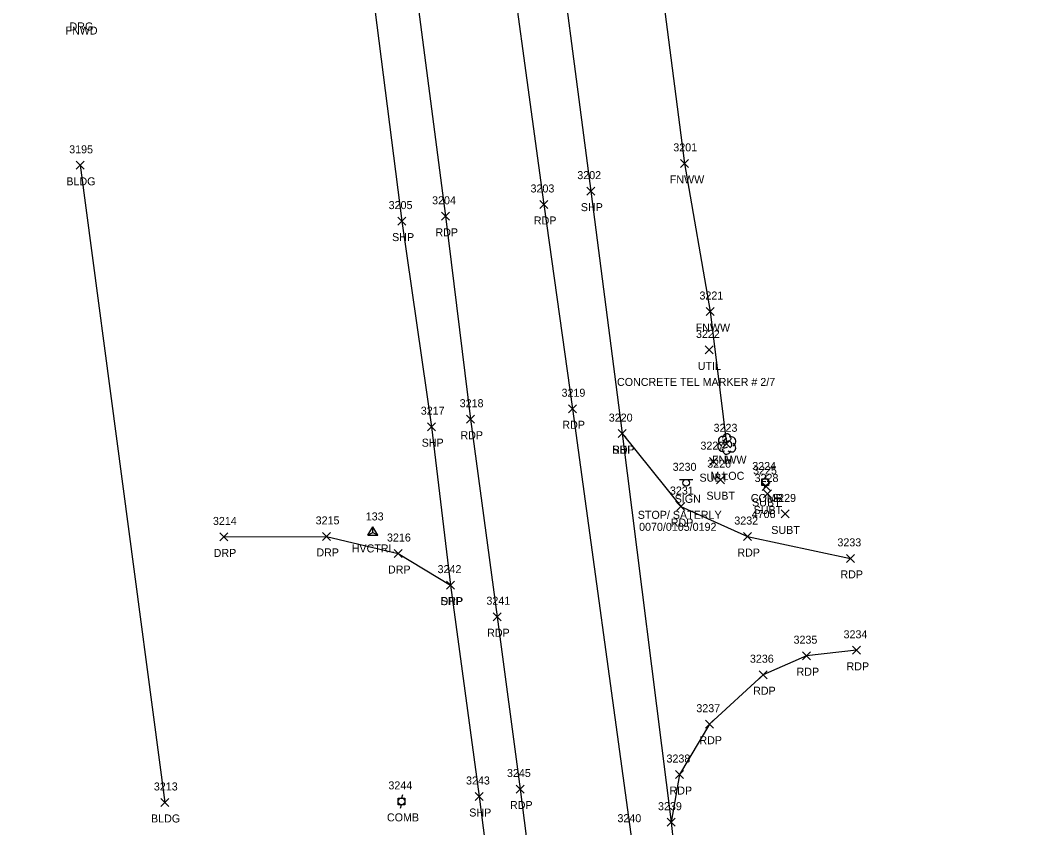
# Model space of a CAD drawing. Extents: x 1443071 to 1445292, y 614024 to 622563.
# Drawn here: x 1444280.5 to 1444535.7, y 616322 to 616523.8 of the extents above; entities that cross this region are included whole.
import ezdxf

# ---------------------------------------------------------------- set-up
doc = ezdxf.new("R2010")
doc.units = 0
for name, color, linetype in [('C_A', 7, 'Continuous'), ('C_I', 7, 'Continuous'), ('CPSM', 7, 'Continuous'), ('L_A', 7, 'Continuous'), ('L_C', 7, 'Continuous'), ('L_I', 7, 'Continuous'), ('L_TIC', 7, 'Continuous'), ('LBC', 7, 'Continuous'), ('LFNC', 7, 'Continuous'), ('LTD', 7, 'Continuous'), ('P_A', 7, 'Continuous'), ('P_I', 7, 'Continuous'), ('P_TIC', 7, 'Continuous'), ('PET', 7, 'Continuous'), ('PSP', 7, 'Continuous'), ('R_A', 7, 'Continuous'), ('R_I', 7, 'Continuous'), ('R_TIC', 7, 'Continuous'), ('RDP', 7, 'Continuous'), ('S_A', 7, 'Continuous'), ('S_C', 7, 'Continuous'), ('S_I', 7, 'Continuous'), ('SSGN', 7, 'Continuous'), ('U_A', 7, 'Continuous'), ('U_C', 7, 'Continuous'), ('U_I', 7, 'Continuous'), ('U_TIC', 7, 'Continuous'), ('UDEFAULT', 7, 'Continuous'), ('UP', 7, 'Continuous')]:
    doc.layers.add(name, color=color, linetype=linetype)

msp = doc.modelspace()

# ---------------------------------------------------------------- linework, layer by layer
at = {"layer": 'CPSM'}
for p, q in [((1444367.35, 616395.09), (1444368.6, 616397.25)), ((1444369.85, 616395.09), (1444368.6, 616397.25)), ((1444368.6, 616395.81), (1444368.6, 616397.25)), ((1444367.35, 616395.09), (1444368.6, 616395.81)), ((1444367.35, 616395.09), (1444369.85, 616395.09)), ((1444368.6, 616395.81), (1444368.6, 616395.81)), ((1444368.6, 616395.81), (1444369.85, 616395.09))]:
    msp.add_line(p, q, dxfattribs=at)
at = {"layer": 'L_TIC'}
for points in [[(1444445.44, 616487.05), (1444447.44, 616489.05)], [(1444447.44, 616487.05), (1444445.44, 616489.05)], [(1444294.39, 616486.56), (1444296.39, 616488.56)], [(1444296.39, 616486.56), (1444294.39, 616488.56)], [(1444451.89, 616450.02), (1444453.89, 616452.02)], [(1444453.89, 616450.02), (1444451.89, 616452.02)], [(1444455.99, 616416.96), (1444457.99, 616418.96)], [(1444457.99, 616416.96), (1444455.99, 616418.96)], [(1444315.55, 616327.32), (1444317.55, 616329.32)], [(1444317.55, 616327.32), (1444315.55, 616329.32)]]:
    msp.add_lwpolyline(points, dxfattribs=at)
at = {"layer": 'LBC'}
msp.add_lwpolyline([(1444295.39, 616487.56), (1444316.55, 616328.32)], dxfattribs=at)
at = {"layer": 'LFNC'}
msp.add_lwpolyline([(1444444.21, 617032.59), (1444396.73, 617023.1), (1444383.68, 617022.43), (1444396.85, 616893.79), (1444402.65, 616848.17), (1444409.06, 616773.1), (1444419.22, 616694.29), (1444436.3, 616566.7), (1444446.44, 616488.05), (1444452.89, 616451.02), (1444456.99, 616417.96)], dxfattribs=at)
at = {"layer": 'LTD'}
msp.add_line((1444456.99, 616417.96), (1444456.99, 616417.96), dxfattribs=at)
msp.add_line((1444456.99, 616417.96), (1444456.99, 616417.96), dxfattribs=at)
msp.add_arc((1444457.04, 616419.4), 1.05, 335.5272, 180.9563, dxfattribs=at)
for centre, major_axis, ratio, start_param, end_param in [((1444456.2, 616418.63), (1.21, -0.51), 0.895232, 1.570796, 4.712389), ((1444455.91, 616417.26), (0.58, -1.04), 0.959034, 3.141593, 6.283185), ((1444456.79, 616418.42), (-0.208, -0.792), 0.645439, 3.141593, 6.283185), ((1444457.49, 616417.8), (-0.5, 0.667), 0.989748, 3.141593, 6.283185), ((1444457.99, 616417.13), (-1.09, 0.79), 0.841452, 1.570796, 4.712389), ((1444458.04, 616418.55), (-1.14, -0.48), 0.949671, 1.570796, 4.712389), ((1444457, 616416.46), (0.26, 1.06), 0.942809, 1.570796, 4.712389), ((1444456.54, 616417.21), (-0.625, -0.083), 0.423636, 0, 3.141593)]:
    msp.add_ellipse(centre, major_axis=major_axis, ratio=ratio, start_param=start_param, end_param=end_param, dxfattribs=at)
at = {"layer": 'P_TIC'}
for points in [[(1444422.01, 616480.11), (1444424.01, 616482.11)], [(1444424.01, 616480.11), (1444422.01, 616482.11)], [(1444410.32, 616476.78), (1444412.32, 616478.78)], [(1444412.32, 616476.78), (1444410.32, 616478.78)], [(1444374.85, 616472.62), (1444376.85, 616474.62)], [(1444376.85, 616472.62), (1444374.85, 616474.62)], [(1444385.72, 616473.82), (1444387.72, 616475.82)], [(1444387.72, 616473.82), (1444385.72, 616475.82)], [(1444417.43, 616425.72), (1444419.43, 616427.72)], [(1444419.43, 616425.72), (1444417.43, 616427.72)], [(1444391.98, 616423.11), (1444393.98, 616425.11)], [(1444393.98, 616423.11), (1444391.98, 616425.11)], [(1444382.24, 616421.24), (1444384.24, 616423.24)], [(1444384.24, 616421.24), (1444382.24, 616423.24)], [(1444429.88, 616419.51), (1444431.88, 616421.51)], [(1444431.88, 616419.51), (1444429.88, 616421.51)], [(1444429.88, 616419.51), (1444431.88, 616421.51)], [(1444431.88, 616419.51), (1444429.88, 616421.51)], [(1444444.52, 616401.28), (1444446.52, 616403.28)], [(1444446.52, 616401.28), (1444444.52, 616403.28)], [(1444461.17, 616393.78), (1444463.17, 616395.78)], [(1444463.17, 616393.78), (1444461.17, 616395.78)], [(1444486.93, 616388.33), (1444488.93, 616390.33)], [(1444488.93, 616388.33), (1444486.93, 616390.33)], [(1444387.01, 616381.64), (1444389.01, 616383.64)], [(1444389.01, 616381.64), (1444387.01, 616383.64)], [(1444398.64, 616373.74), (1444400.64, 616375.74)], [(1444400.64, 616373.74), (1444398.64, 616375.74)], [(1444488.47, 616365.35), (1444490.47, 616367.35)], [(1444490.47, 616365.35), (1444488.47, 616367.35)], [(1444475.97, 616364), (1444477.97, 616366)], [(1444477.97, 616364), (1444475.97, 616366)], [(1444465.12, 616359.25), (1444467.12, 616361.25)], [(1444467.12, 616359.25), (1444465.12, 616361.25)], [(1444451.68, 616346.88), (1444453.68, 616348.88)], [(1444453.68, 616346.88), (1444451.68, 616348.88)], [(1444444.22, 616334.3), (1444446.22, 616336.3)], [(1444446.22, 616334.3), (1444444.22, 616336.3)], [(1444394.12, 616328.81), (1444396.12, 616330.81)], [(1444396.12, 616328.81), (1444394.12, 616330.81)], [(1444404.35, 616330.68), (1444406.35, 616332.68)], [(1444406.35, 616330.68), (1444404.35, 616332.68)], [(1444442.11, 616322.39), (1444444.11, 616324.39)], [(1444444.11, 616322.39), (1444442.11, 616324.39)], [(1444442.11, 616322.39), (1444444.11, 616324.39)], [(1444444.11, 616322.39), (1444442.11, 616324.39)]]:
    msp.add_lwpolyline(points, dxfattribs=at)
at = {"layer": 'PET'}
for points in [[(1444290.04, 617226.49), (1444293.29, 617200.68), (1444305.86, 617102.26), (1444318.1, 617012.36), (1444328.61, 616929.53), (1444340.48, 616832.7), (1444349.36, 616766.46), (1444359.48, 616687.73), (1444375.76, 616559.26), (1444386.72, 616474.82), (1444392.98, 616424.11), (1444399.64, 616374.74), (1444405.35, 616331.68), (1444416.25, 616246.74), (1444430.45, 616134.64), (1444440.68, 616052.2), (1444460.71, 615897.87), (1444469.48, 615825.17), (1444479.32, 615749.85), (1444490.82, 615663.43), (1444501.1, 615593.99)], [(1444314.9, 617227.6), (1444331.28, 617099.37), (1444342.74, 617014.98), (1444353.45, 616933.43), (1444365.99, 616834.42), (1444373.87, 616769.68), (1444384.25, 616690.54), (1444399.86, 616561.36), (1444411.32, 616477.78), (1444418.43, 616426.72), (1444433.04, 616320.39), (1444440.5, 616248.61), (1444455.15, 616137.88), (1444465.57, 616054.84), (1444485.3, 615900.9), (1444494.14, 615826.26), (1444503.74, 615751.94), (1444515.41, 615666.64), (1444525.64, 615597.72)], [(1444430.88, 616420.51), (1444445.52, 616402.28), (1444462.17, 616394.78), (1444487.93, 616389.33)], [(1444489.47, 616366.35), (1444476.97, 616365), (1444466.12, 616360.25), (1444452.68, 616347.88), (1444445.22, 616335.3), (1444443.11, 616323.39)]]:
    msp.add_lwpolyline(points, dxfattribs=at)
at = {"layer": 'PSP'}
for points in [[(1444325.72, 617229.34), (1444331.18, 617190.03), (1444341.63, 617111.11), (1444353.65, 617016.1), (1444364.55, 616934.22), (1444377.14, 616835.48), (1444385.64, 616770.75), (1444395.97, 616692.96), (1444412.43, 616562.03), (1444423.01, 616481.11), (1444430.88, 616420.51), (1444443.11, 616323.39), (1444448.99, 616268.44), (1444454, 616230.8), (1444465.61, 616141.36), (1444476.5, 616056.13), (1444483.28, 615998.72), (1444489.46, 615946.55), (1444495.54, 615902.14), (1444505.18, 615827.19), (1444514.81, 615753.2), (1444525.85, 615667.7), (1444535.69, 615600.77)], [(1444280.5, 617226.12), (1444283.66, 617200.61), (1444293.17, 617127.11), (1444296.38, 617100.83), (1444308.28, 617010.91), (1444318.74, 616928.98), (1444325.56, 616872.02), (1444335.05, 616795.34), (1444338.72, 616765.27), (1444349.45, 616686.56), (1444353.22, 616653.3), (1444364.91, 616559.25), (1444375.85, 616473.62), (1444383.24, 616422.24), (1444388.01, 616382.64), (1444395.12, 616329.81), (1444406.01, 616244.88), (1444420.16, 616134.13), (1444430.49, 616051.12), (1444450.17, 615896.86), (1444459.96, 615823.48), (1444469.66, 615749), (1444481.34, 615661.86), (1444491.6, 615592.34)]]:
    msp.add_lwpolyline(points, dxfattribs=at)
at = {"layer": 'R_TIC'}
for points in [[(1444330.3, 616393.68), (1444332.3, 616395.68)], [(1444332.3, 616393.68), (1444330.3, 616395.68)], [(1444355.98, 616393.82), (1444357.98, 616395.82)], [(1444357.98, 616393.82), (1444355.98, 616395.82)], [(1444373.86, 616389.54), (1444375.86, 616391.54)], [(1444375.86, 616389.54), (1444373.86, 616391.54)], [(1444387.01, 616381.64), (1444389.01, 616383.64)], [(1444389.01, 616381.64), (1444387.01, 616383.64)]]:
    msp.add_lwpolyline(points, dxfattribs=at)
at = {"layer": 'RDP'}
msp.add_lwpolyline([(1444331.3, 616394.68), (1444356.98, 616394.82), (1444374.86, 616390.54), (1444388.01, 616382.64)], dxfattribs=at)
at = {"layer": 'SSGN'}
for p, q in [((1444445.22, 616409.06), (1444448.55, 616409.06)), ((1444446.87, 616408.23), (1444446.87, 616408.23))]:
    msp.add_line(p, q, dxfattribs=at)
msp.add_circle((1444446.87, 616408.23), 0.833, dxfattribs=at)
at = {"layer": 'U_TIC'}
for points in [[(1444452.7, 616412.5), (1444454.7, 616414.5)], [(1444454.7, 616412.5), (1444452.7, 616414.5)], [(1444454.44, 616407.99), (1444456.44, 616409.99)], [(1444456.44, 616407.99), (1444454.44, 616409.99)], [(1444465.86, 616406.32), (1444467.86, 616408.32)], [(1444467.86, 616406.32), (1444465.86, 616408.32)], [(1444466.24, 616404.42), (1444468.24, 616406.42)], [(1444468.24, 616404.42), (1444466.24, 616406.42)], [(1444470.65, 616399.43), (1444472.65, 616401.43)], [(1444472.65, 616399.43), (1444470.65, 616401.43)]]:
    msp.add_lwpolyline(points, dxfattribs=at)
at = {"layer": 'UDEFAULT'}
for points in [[(1444451.59, 616440.42), (1444453.59, 616442.42)], [(1444453.59, 616440.42), (1444451.59, 616442.42)]]:
    msp.add_lwpolyline(points, dxfattribs=at)
at = {"layer": 'UP'}
for p, q in [((1444466.9, 616410.07), (1444466.65, 616409.24)), ((1444465.81, 616407.57), (1444465.81, 616409.24)), ((1444465.81, 616409.24), (1444467.48, 616409.24)), ((1444467.48, 616407.57), (1444465.81, 616407.57)), ((1444466.4, 616406.74), (1444466.65, 616407.57)), ((1444466.65, 616408.41), (1444466.65, 616408.41)), ((1444467.48, 616409.24), (1444467.48, 616407.57)), ((1444374.88, 616327.75), (1444374.88, 616329.42)), ((1444374.88, 616329.42), (1444376.55, 616329.42)), ((1444375.97, 616330.25), (1444375.72, 616329.42)), ((1444375.72, 616328.59), (1444375.72, 616328.59)), ((1444376.55, 616329.42), (1444376.55, 616327.75)), ((1444376.55, 616327.75), (1444374.88, 616327.75)), ((1444375.47, 616326.92), (1444375.72, 616327.75))]:
    msp.add_line(p, q, dxfattribs=at)
for centre in [(1444466.65, 616408.41), (1444375.72, 616328.59)]:
    msp.add_circle(centre, 0.833, dxfattribs=at)

# ---------------------------------------------------------------- texts
at = {"layer": 'C_A'}
msp.add_text('HVCTRL', height=2, dxfattribs=at).set_placement((1444363.29, 616390.81))
at = {"layer": 'C_I'}
msp.add_text('133', height=2, dxfattribs=at).set_placement((1444366.8, 616398.81))
at = {"layer": 'L_A'}
for s, p in [('FNWD', (1444291.76, 616520.25)), ('BLDG', (1444291.98, 616482.56)), ('FNWW', (1444442.78, 616483.05)), ('FNWW', (1444449.24, 616446.02)), ('FNWW', (1444453.34, 616412.96)), ('H', (1444456.43, 616412.96)), ('BLDG', (1444313.14, 616323.32))]:
    msp.add_text(s, height=2, dxfattribs=at).set_placement(p)
at = {"layer": 'L_C'}
msp.add_text('M.LOC', height=2, dxfattribs=at).set_placement((1444452.94, 616408.96))
at = {"layer": 'L_I'}
for s, p in [('3195', (1444292.69, 616490.56)), ('3201', (1444443.66, 616491.05)), ('3221', (1444450.2, 616454.02)), ('3223', (1444453.73, 616420.96)), ('3223', (1444453.73, 616420.96)), ('3213', (1444313.85, 616331.32))]:
    msp.add_text(s, height=2, dxfattribs=at).set_placement(p)
at = {"layer": 'P_A'}
for s, p in [('SHP', (1444420.55, 616476.11)), ('RDP', (1444408.81, 616472.78)), ('RDP', (1444384.21, 616469.82)), ('SHP', (1444373.39, 616468.62)), ('RDP', (1444415.92, 616421.72)), ('RDP', (1444390.46, 616419.11)), ('SHP', (1444380.78, 616417.24)), ('SHP', (1444428.42, 616415.51)), ('RDP', (1444428.37, 616415.51)), ('RDP', (1444443.01, 616397.28)), ('RDP', (1444459.66, 616389.78)), ('RDP', (1444485.42, 616384.33)), ('SHP', (1444385.54, 616377.64)), ('RDP', (1444397.13, 616369.74)), ('RDP', (1444474.46, 616360)), ('RDP', (1444486.95, 616361.35)), ('RDP', (1444463.61, 616355.25)), ('RDP', (1444450.17, 616342.88)), ('RDP', (1444442.71, 616330.3)), ('RDP', (1444402.84, 616326.68)), ('SHP', (1444392.66, 616324.81))]:
    msp.add_text(s, height=2, dxfattribs=at).set_placement(p)
at = {"layer": 'P_I'}
for s, p in [('3202', (1444419.67, 616484.11)), ('3203', (1444407.98, 616480.78)), ('3205', (1444372.52, 616476.62)), ('3204', (1444383.38, 616477.82)), ('3219', (1444415.73, 616429.72)), ('3218', (1444390.28, 616427.11)), ('3217', (1444380.55, 616425.24)), ('3220', (1444427.54, 616423.51)), ('3220', (1444427.54, 616423.51)), ('3231', (1444442.82, 616405.28)), ('3232', (1444458.91, 616397.78)), ('3233', (1444484.67, 616392.33)), ('3242', (1444384.75, 616385.64)), ('3241', (1444396.95, 616377.74)), ('3235', (1444473.71, 616368)), ('3234', (1444486.21, 616369.35)), ('3236', (1444462.81, 616363.25)), ('3237', (1444449.42, 616350.88)), ('3238', (1444441.96, 616338.3)), ('3245', (1444402.09, 616334.68)), ('3243', (1444391.86, 616332.81)), ('3239', (1444439.84, 616326.39)), ('3239', (1444439.84, 616326.39)), ('3240', (1444429.7, 616323.39))]:
    msp.add_text(s, height=2, dxfattribs=at).set_placement(p)
at = {"layer": 'R_A'}
for s, p in [('DRG', (1444292.77, 616521.27)), ('DRP', (1444328.79, 616389.68)), ('DRP', (1444354.46, 616389.82)), ('DRP', (1444372.35, 616385.54)), ('DRP', (1444385.5, 616377.64))]:
    msp.add_text(s, height=2, dxfattribs=at).set_placement(p)
at = {"layer": 'R_I'}
for s, p in [('3214', (1444328.61, 616397.68)), ('3215', (1444354.28, 616397.82)), ('3216', (1444372.11, 616393.54)), ('3242', (1444384.75, 616385.64))]:
    msp.add_text(s, height=2, dxfattribs=at).set_placement(p)
at = {"layer": 'S_A'}
msp.add_text('SIGN', height=2, dxfattribs=at).set_placement((1444444, 616403.21))
at = {"layer": 'S_C'}
for s, p in [('STOP/ SATERLY', (1444434.78, 616399.21)), ('0070/0105/0192', (1444435.11, 616396.21))]:
    msp.add_text(s, height=2, dxfattribs=at).set_placement(p)
at = {"layer": 'S_I'}
msp.add_text('3230', height=2, dxfattribs=at).set_placement((1444443.5, 616411.21))
at = {"layer": 'U_A'}
for s, p in [('UTIL', (1444449.76, 616436.42)), ('SUBT', (1444450.2, 616408.5)), ('SUBT', (1444451.94, 616403.99)), ('COMB', (1444463.03, 616403.41)), ('SUBT', (1444463.35, 616402.32)), ('SUBT', (1444463.73, 616400.42)), ('SUBT', (1444468.14, 616395.43)), ('COMB', (1444372.1, 616323.59))]:
    msp.add_text(s, height=2, dxfattribs=at).set_placement(p)
at = {"layer": 'U_C'}
for s, p in [('CONCRETE TEL MARKER # 2/7', (1444429.59, 616432.42)), ('4706', (1444463.25, 616399.41))]:
    msp.add_text(s, height=2, dxfattribs=at).set_placement(p)
at = {"layer": 'U_I'}
for s, p in [('3222', (1444449.33, 616444.42)), ('3227', (1444450.44, 616416.5)), ('3226', (1444452.13, 616411.99)), ('3224', (1444463.39, 616411.41)), ('3225', (1444463.6, 616410.32)), ('3228', (1444463.98, 616408.42)), ('3229', (1444468.38, 616403.43)), ('3244', (1444372.46, 616331.59))]:
    msp.add_text(s, height=2, dxfattribs=at).set_placement(p)

doc.saveas('drawing.dxf')
